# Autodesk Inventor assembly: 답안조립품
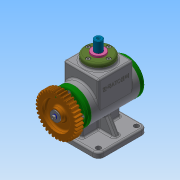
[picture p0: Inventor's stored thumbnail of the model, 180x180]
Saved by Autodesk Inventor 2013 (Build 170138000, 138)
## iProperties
Created: 2019-01
Part Number: 답안조립품
Document SubType Name: Assembly
Designer: Gpr
Mass: 1743.45 g
Surface Area: 1517.22 cm^2
Volume: 492.002 cm^3
Density: 3.54358 g/cm^3
Author: Gpr
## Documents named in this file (18)
- C:\Users\Administrator\Desktop\390107V1047\답안조립품.iam
- C:\Users\Administrator\Desktop\390107V1047\본체.ipt
- C:\Users\Administrator\Desktop\390107V1047\뒤커버.ipt
- C:\Users\Administrator\Desktop\390107V1047\베어링 6203.ipt
- C:\Users\Administrator\Desktop\390107V1047\볼트 M4.ipt
- C:\Users\Administrator\Desktop\390107V1047\스퍼기어.ipt
- C:\Users\Administrator\Desktop\390107V1047\스프링와셔.ipt
- C:\Users\Administrator\Desktop\390107V1047\앞커버.ipt
- C:\Users\Administrator\Desktop\390107V1047\오일 실 17 30 5.ipt
- C:\Users\Administrator\Desktop\390107V1047\키 4x4x12.ipt
- C:\Users\Administrator\Desktop\390107V1047\편심축.ipt
- C:\Users\Administrator\Desktop\390107V1047\평와셔.ipt
- C:\Users\Administrator\Desktop\390107V1047\멈춤링.ipt
- C:\Users\Administrator\Desktop\390107V1047\부시.ipt
- C:\Users\Administrator\Desktop\390107V1047\상부커버.ipt
- C:\Users\Administrator\Desktop\390107V1047\스프링조립용 와셔.ipt
- C:\Users\Administrator\Desktop\390107V1047\슬라이더.ipt
- C:\Users\Administrator\Desktop\390107V1047\가변스프링.ipt
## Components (1 placed, 1 different names)
1. 가변스프링:1
